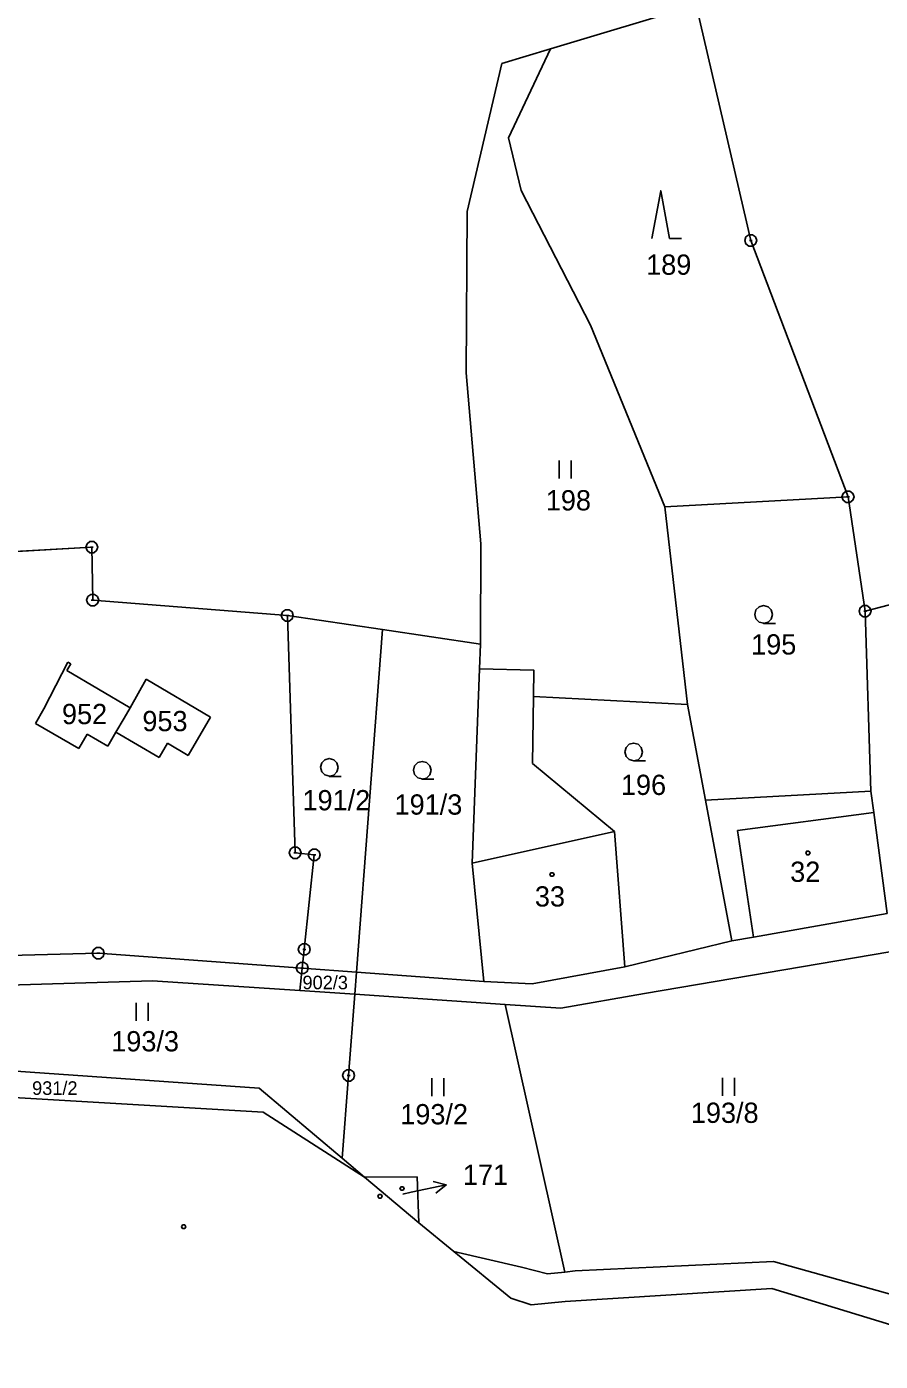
# Model space of a CAD drawing. Extents: x -580551 to -575069, y -1073031 to -1067931.
# Drawn here: x -576922.3 to -576850.7, y -1069930.4 to -1069818.4 of the extents above; entities that cross this region are included whole.
import ezdxf

# ---------------------------------------------------------------- set-up
doc = ezdxf.new("R2010")
doc.units = 0
for name, color, linetype in [('Druh pozemku', 7, 'Continuous'), ('Geodetické body', 7, 'Continuous'), ('Hranice z DKM', 7, 'Continuous'), ('Katastrální hranice', 7, 'Continuous'), ('Parcela', 7, 'Continuous'), ('Parcelní číslo', 7, 'Continuous'), ('Parcelní číslo_stavba', 7, 'Continuous'), ('Pomocná vrstva', 7, 'Continuous'), ('SR - hranice státu', 7, 'Continuous'), ('Vnitřní kresba', 7, 'Continuous'), ('Vrstva 6', 7, 'Continuous')]:
    doc.layers.add(name, color=color, linetype=linetype)

msp = doc.modelspace()

# ---------------------------------------------------------------- linework, layer by layer
at = {"layer": 'Druh pozemku'}
for p, q in [((-576877.6, -1069854.79), (-576877.6, -1069856.29)), ((-576876.6, -1069856.29), (-576876.6, -1069854.79)), ((-576913.12, -1069900.29), (-576913.12, -1069901.79)), ((-576912.12, -1069901.79), (-576912.12, -1069900.29)), ((-576888.3, -1069906.61), (-576888.3, -1069908.11)), ((-576887.3, -1069908.11), (-576887.3, -1069906.61)), ((-576863.9, -1069906.59), (-576863.9, -1069908.09)), ((-576862.9, -1069908.09), (-576862.9, -1069906.59))]:
    msp.add_line(p, q, dxfattribs=at)
for points in [[(-576869.84, -1069836.16), (-576869.09, -1069832.16), (-576868.34, -1069836.16), (-576867.34, -1069836.16)], [(-576860.44, -1069868.44), (-576860.82, -1069868.34), (-576861.09, -1069868.07), (-576861.19, -1069867.7), (-576861.09, -1069867.33), (-576860.82, -1069867.06), (-576860.45, -1069866.96), (-576860.08, -1069867.06), (-576859.81, -1069867.33), (-576859.71, -1069867.71), (-576859.81, -1069868.09), (-576860.08, -1069868.36), (-576860.46, -1069868.46), (-576859.46, -1069868.46)], [(-576871.35, -1069879.98), (-576871.73, -1069879.88), (-576872, -1069879.61), (-576872.1, -1069879.24), (-576872, -1069878.87), (-576871.73, -1069878.6), (-576871.36, -1069878.5), (-576870.99, -1069878.6), (-576870.72, -1069878.87), (-576870.62, -1069879.25), (-576870.72, -1069879.63), (-576870.99, -1069879.9), (-576871.37, -1069880), (-576870.37, -1069880)], [(-576896.9, -1069881.27), (-576897.28, -1069881.17), (-576897.55, -1069880.9), (-576897.65, -1069880.53), (-576897.55, -1069880.16), (-576897.28, -1069879.89), (-576896.91, -1069879.79), (-576896.54, -1069879.89), (-576896.27, -1069880.16), (-576896.17, -1069880.54), (-576896.27, -1069880.92), (-576896.54, -1069881.19), (-576896.92, -1069881.29), (-576895.92, -1069881.29)], [(-576889.1, -1069881.51), (-576889.48, -1069881.41), (-576889.75, -1069881.14), (-576889.85, -1069880.77), (-576889.75, -1069880.4), (-576889.48, -1069880.13), (-576889.11, -1069880.03), (-576888.74, -1069880.13), (-576888.47, -1069880.4), (-576888.37, -1069880.78), (-576888.47, -1069881.16), (-576888.74, -1069881.43), (-576889.12, -1069881.53), (-576888.12, -1069881.53)]]:
    msp.add_lwpolyline(points, dxfattribs=at)
for points in [[(-576856.64, -1069887.56), (-576856.55, -1069887.71), (-576856.64, -1069887.86), (-576856.82, -1069887.86), (-576856.91, -1069887.71), (-576856.82, -1069887.56)], [(-576878.12, -1069889.37), (-576878.03, -1069889.52), (-576878.12, -1069889.67), (-576878.3, -1069889.67), (-576878.39, -1069889.52), (-576878.3, -1069889.37)], [(-576892.56, -1069916.37), (-576892.47, -1069916.52), (-576892.56, -1069916.67), (-576892.74, -1069916.67), (-576892.83, -1069916.52), (-576892.74, -1069916.37)], [(-576890.71, -1069915.71), (-576890.62, -1069915.86), (-576890.71, -1069916.01), (-576890.89, -1069916.01), (-576890.98, -1069915.86), (-576890.89, -1069915.71)], [(-576909.05, -1069918.92), (-576908.96, -1069919.07), (-576909.05, -1069919.22), (-576909.23, -1069919.22), (-576909.32, -1069919.07), (-576909.23, -1069918.92)]]:
    msp.add_lwpolyline(points, close=True, dxfattribs=at)
at = {"layer": 'Geodetické body'}
for p, q in [((-576861.64, -1069836.34), (-576861.4, -1069836.34)), ((-576853.48, -1069857.85), (-576853.24, -1069857.85)), ((-576916.96, -1069862.07), (-576916.72, -1069862.07)), ((-576916.89, -1069866.51), (-576916.65, -1069866.51)), ((-576900.55, -1069867.8), (-576900.31, -1069867.8)), ((-576852.04, -1069867.44), (-576851.8, -1069867.44)), ((-576899.89, -1069887.71), (-576899.65, -1069887.71)), ((-576898.29, -1069887.88), (-576898.05, -1069887.88)), ((-576916.42, -1069896.13), (-576916.18, -1069896.13)), ((-576899.13, -1069895.81), (-576898.89, -1069895.81)), ((-576899.3, -1069897.38), (-576899.06, -1069897.38)), ((-576895.41, -1069906.39), (-576895.17, -1069906.39))]:
    msp.add_line(p, q, dxfattribs=at)
for points in [[(-576861.37, -1069835.86), (-576861.12, -1069836.04), (-576861.02, -1069836.33), (-576861.12, -1069836.62), (-576861.37, -1069836.8), (-576861.68, -1069836.8), (-576861.93, -1069836.62), (-576862.03, -1069836.33), (-576861.93, -1069836.04), (-576861.68, -1069835.86)], [(-576853.21, -1069857.37), (-576852.96, -1069857.55), (-576852.86, -1069857.84), (-576852.96, -1069858.13), (-576853.21, -1069858.31), (-576853.52, -1069858.31), (-576853.77, -1069858.13), (-576853.87, -1069857.84), (-576853.77, -1069857.55), (-576853.52, -1069857.37)], [(-576916.69, -1069861.59), (-576916.44, -1069861.77), (-576916.34, -1069862.06), (-576916.44, -1069862.35), (-576916.69, -1069862.53), (-576917, -1069862.53), (-576917.25, -1069862.35), (-576917.35, -1069862.06), (-576917.25, -1069861.77), (-576917, -1069861.59)], [(-576916.62, -1069866.03), (-576916.37, -1069866.21), (-576916.27, -1069866.5), (-576916.37, -1069866.79), (-576916.62, -1069866.97), (-576916.93, -1069866.97), (-576917.18, -1069866.79), (-576917.28, -1069866.5), (-576917.18, -1069866.21), (-576916.93, -1069866.03)], [(-576900.28, -1069867.32), (-576900.03, -1069867.5), (-576899.93, -1069867.79), (-576900.03, -1069868.08), (-576900.28, -1069868.26), (-576900.59, -1069868.26), (-576900.84, -1069868.08), (-576900.94, -1069867.79), (-576900.84, -1069867.5), (-576900.59, -1069867.32)], [(-576851.77, -1069866.96), (-576851.52, -1069867.14), (-576851.42, -1069867.43), (-576851.52, -1069867.72), (-576851.77, -1069867.9), (-576852.08, -1069867.9), (-576852.33, -1069867.72), (-576852.43, -1069867.43), (-576852.33, -1069867.14), (-576852.08, -1069866.96)], [(-576899.62, -1069887.23), (-576899.37, -1069887.41), (-576899.27, -1069887.7), (-576899.37, -1069887.99), (-576899.62, -1069888.17), (-576899.93, -1069888.17), (-576900.18, -1069887.99), (-576900.28, -1069887.7), (-576900.18, -1069887.41), (-576899.93, -1069887.23)], [(-576898.02, -1069887.4), (-576897.77, -1069887.58), (-576897.67, -1069887.87), (-576897.77, -1069888.16), (-576898.02, -1069888.34), (-576898.33, -1069888.34), (-576898.58, -1069888.16), (-576898.68, -1069887.87), (-576898.58, -1069887.58), (-576898.33, -1069887.4)], [(-576898.86, -1069895.33), (-576898.61, -1069895.51), (-576898.51, -1069895.8), (-576898.61, -1069896.09), (-576898.86, -1069896.27), (-576899.17, -1069896.27), (-576899.42, -1069896.09), (-576899.52, -1069895.8), (-576899.42, -1069895.51), (-576899.17, -1069895.33)], [(-576916.15, -1069895.65), (-576915.9, -1069895.83), (-576915.8, -1069896.12), (-576915.9, -1069896.41), (-576916.15, -1069896.59), (-576916.46, -1069896.59), (-576916.71, -1069896.41), (-576916.81, -1069896.12), (-576916.71, -1069895.83), (-576916.46, -1069895.65)], [(-576899.03, -1069896.9), (-576898.78, -1069897.08), (-576898.68, -1069897.37), (-576898.78, -1069897.66), (-576899.03, -1069897.84), (-576899.34, -1069897.84), (-576899.59, -1069897.66), (-576899.69, -1069897.37), (-576899.59, -1069897.08), (-576899.34, -1069896.9)], [(-576895.14, -1069905.91), (-576894.89, -1069906.09), (-576894.79, -1069906.38), (-576894.89, -1069906.67), (-576895.14, -1069906.85), (-576895.45, -1069906.85), (-576895.7, -1069906.67), (-576895.8, -1069906.38), (-576895.7, -1069906.09), (-576895.45, -1069905.91)]]:
    msp.add_lwpolyline(points, close=True, dxfattribs=at)
at = {"layer": 'Hranice z DKM'}
msp.add_lwpolyline([(-576884.21, -1069870.2), (-576884.19, -1069861.78), (-576885.42, -1069847.43), (-576885.34, -1069833.9), (-576882.42, -1069821.5), (-576878.33, -1069820.27), (-576881.87, -1069827.71), (-576880.79, -1069832.14), (-576874.99, -1069843.44), (-576868.75, -1069858.68)], dxfattribs=at)
at = {"layer": 'Katastrální hranice'}
for p, q in [((-576902.47, -1069909.45), (-576936.44, -1069907.45)), ((-576893.96, -1069914.9), (-576902.47, -1069909.45)), ((-576889.39, -1069918.74), (-576893.96, -1069914.9)), ((-576886.45, -1069921.15), (-576889.39, -1069918.74)), ((-576881.68, -1069925.06), (-576886.45, -1069921.15)), ((-576859.77, -1069924.26), (-576877.11, -1069925.34)), ((-576839.68, -1069930.36), (-576859.77, -1069924.26)), ((-576879.96, -1069925.62), (-576881.68, -1069925.06)), ((-576877.11, -1069925.34), (-576879.96, -1069925.62))]:
    msp.add_line(p, q, dxfattribs=at)
at = {"layer": 'Parcela'}
for p, q in [((-576866.12, -1069816.6), (-576878.33, -1069820.27)), ((-576866.12, -1069816.6), (-576861.52, -1069836.34)), ((-576878.33, -1069820.27), (-576882.42, -1069821.5)), ((-576881.87, -1069827.71), (-576878.33, -1069820.27)), ((-576882.42, -1069821.5), (-576885.34, -1069833.9)), ((-576880.79, -1069832.14), (-576881.87, -1069827.71)), ((-576874.99, -1069843.44), (-576880.79, -1069832.14)), ((-576885.34, -1069833.9), (-576885.42, -1069847.43)), ((-576861.52, -1069836.34), (-576853.36, -1069857.85)), ((-576868.75, -1069858.68), (-576874.99, -1069843.44)), ((-576885.42, -1069847.43), (-576884.19, -1069861.78)), ((-576810.54, -1069856.67), (-576851.92, -1069867.44)), ((-576853.36, -1069857.85), (-576868.75, -1069858.68)), ((-576853.36, -1069857.85), (-576851.92, -1069867.44)), ((-576868.75, -1069858.68), (-576866.85, -1069875.26)), ((-576926.56, -1069862.61), (-576916.84, -1069862.07)), ((-576916.84, -1069862.07), (-576916.77, -1069866.51)), ((-576884.21, -1069870.2), (-576884.19, -1069861.78)), ((-576916.77, -1069866.51), (-576900.43, -1069867.8)), ((-576900.43, -1069867.8), (-576899.77, -1069887.71)), ((-576900.43, -1069867.8), (-576892.44, -1069868.98)), ((-576851.92, -1069867.44), (-576851.44, -1069882.54)), ((-576892.44, -1069868.98), (-576894.63, -1069897.71)), ((-576892.44, -1069868.98), (-576884.21, -1069870.2)), ((-576884.29, -1069872.27), (-576884.21, -1069870.2)), ((-576920.87, -1069875.63), (-576918.87, -1069871.7)), ((-576918.62, -1069871.86), (-576918.87, -1069871.7)), ((-576918.95, -1069872.41), (-576918.62, -1069871.86)), ((-576913.64, -1069875.53), (-576918.95, -1069872.41)), ((-576884.91, -1069888.57), (-576884.29, -1069872.27)), ((-576879.74, -1069872.37), (-576884.29, -1069872.27)), ((-576879.77, -1069874.59), (-576879.74, -1069872.37)), ((-576913.64, -1069875.53), (-576912.28, -1069873.13)), ((-576912.28, -1069873.13), (-576906.87, -1069876.31)), ((-576879.85, -1069880.22), (-576879.77, -1069874.59)), ((-576866.85, -1069875.26), (-576879.77, -1069874.59)), ((-576921.58, -1069876.85), (-576920.87, -1069875.63)), ((-576914.13, -1069876.4), (-576913.64, -1069875.53)), ((-576906.87, -1069876.31), (-576908.76, -1069879.53)), ((-576866.85, -1069875.26), (-576865.34, -1069883.29)), ((-576917.94, -1069878.95), (-576921.58, -1069876.85)), ((-576914.82, -1069877.59), (-576914.13, -1069876.4)), ((-576917.24, -1069877.75), (-576917.94, -1069878.95)), ((-576915.5, -1069878.76), (-576917.24, -1069877.75)), ((-576914.82, -1069877.59), (-576915.5, -1069878.76)), ((-576911.2, -1069879.7), (-576914.82, -1069877.59)), ((-576910.5, -1069878.51), (-576911.2, -1069879.7)), ((-576908.76, -1069879.53), (-576910.5, -1069878.51)), ((-576872.98, -1069885.92), (-576879.85, -1069880.22)), ((-576851.44, -1069882.54), (-576865.34, -1069883.29)), ((-576851.44, -1069882.54), (-576851.2, -1069884.33)), ((-576865.34, -1069883.29), (-576863.13, -1069895.1)), ((-576851.2, -1069884.33), (-576850.08, -1069892.79)), ((-576872.11, -1069897.27), (-576872.98, -1069885.92)), ((-576899.77, -1069887.71), (-576898.17, -1069887.88)), ((-576898.17, -1069887.88), (-576899.01, -1069895.81)), ((-576883.93, -1069898.49), (-576884.91, -1069888.57)), ((-576850.08, -1069892.79), (-576861.3, -1069894.78)), ((-576863.13, -1069895.1), (-576872.11, -1069897.27)), ((-576861.3, -1069894.78), (-576863.13, -1069895.1)), ((-576916.3, -1069896.13), (-576949.74, -1069896.96)), ((-576899.18, -1069897.38), (-576916.3, -1069896.13)), ((-576899.01, -1069895.81), (-576899.18, -1069897.38)), ((-576849.85, -1069896), (-576870.44, -1069899.5)), ((-576899.18, -1069897.38), (-576899.39, -1069899.26)), ((-576899.18, -1069897.38), (-576894.63, -1069897.71)), ((-576879.87, -1069898.69), (-576872.11, -1069897.27)), ((-576911.76, -1069898.43), (-576931.95, -1069899.07)), ((-576911.76, -1069898.43), (-576899.39, -1069899.26)), ((-576894.63, -1069897.71), (-576894.77, -1069899.57)), ((-576894.63, -1069897.71), (-576883.93, -1069898.49)), ((-576883.93, -1069898.49), (-576879.87, -1069898.69)), ((-576899.39, -1069899.26), (-576894.77, -1069899.57)), ((-576894.77, -1069899.57), (-576895.29, -1069906.39)), ((-576894.77, -1069899.57), (-576882.15, -1069900.42)), ((-576870.44, -1069899.5), (-576877.48, -1069900.73)), ((-576882.15, -1069900.42), (-576877.48, -1069900.73)), ((-576934.29, -1069905.26), (-576902.79, -1069907.45)), ((-576895.29, -1069906.39), (-576895.82, -1069913.33)), ((-576895.82, -1069913.33), (-576902.79, -1069907.45)), ((-576893.96, -1069914.9), (-576895.82, -1069913.33)), ((-576889.52, -1069914.89), (-576893.96, -1069914.9)), ((-576889.52, -1069914.89), (-576889.39, -1069918.74)), ((-576880.78, -1069922.45), (-576886.45, -1069921.15)), ((-576859.63, -1069921.98), (-576876.27, -1069922.78)), ((-576840.51, -1069927.32), (-576859.63, -1069921.98)), ((-576878.58, -1069923.03), (-576880.78, -1069922.45)), ((-576877.13, -1069922.87), (-576878.58, -1069923.03)), ((-576876.27, -1069922.78), (-576877.13, -1069922.87))]:
    msp.add_line(p, q, dxfattribs=at)
at = {"layer": 'Pomocná vrstva'}
for p in [(-576890.75, -1069916.33), (-576887.094, -1069915.562)]:
    msp.add_line(p, (-576890.03, -1069916.18), dxfattribs=at)
msp.add_lwpolyline([(-576888.176, -1069915.278), (-576887.094, -1069915.562), (-576887.97, -1069916.257)], dxfattribs=at)
at = {"layer": 'SR - hranice státu'}
for points in [[(-576851.92, -1069867.44), (-576810.54, -1069856.67), (-576816.53, -1069845.21), (-576822.88, -1069828.95)], [(-576868.75, -1069858.68), (-576853.36, -1069857.85), (-576851.92, -1069867.44)], [(-576884.21, -1069870.2), (-576884.29, -1069872.27), (-576879.74, -1069872.37), (-576879.77, -1069874.59), (-576866.85, -1069875.26), (-576868.75, -1069858.68)], [(-576942.98, -1069866), (-576926.45, -1069866.31), (-576926.56, -1069862.61), (-576916.84, -1069862.07), (-576916.77, -1069866.51), (-576900.43, -1069867.8)], [(-576900.43, -1069867.8), (-576892.44, -1069868.98), (-576884.21, -1069870.2)]]:
    msp.add_lwpolyline(points, dxfattribs=at)
at = {"layer": 'Vnitřní kresba'}
for p, q in [((-576851.2, -1069884.33), (-576862.65, -1069885.83)), ((-576884.91, -1069888.57), (-576872.98, -1069885.92)), ((-576862.65, -1069885.83), (-576861.3, -1069894.78))]:
    msp.add_line(p, q, dxfattribs=at)
at = {"layer": 'Vrstva 6'}
msp.add_line((-576877.13, -1069922.87), (-576882.15, -1069900.42), dxfattribs=at)

# ---------------------------------------------------------------- texts
at = {"layer": 'Parcelní číslo'}
for s, height, p in [('189', 1.7, (-576870.311, -1069839.21)), ('198', 1.7, (-576878.735, -1069858.98)), ('195', 1.7, (-576861.499, -1069871.07)), ('952', 1.7, (-576919.351, -1069876.91)), ('953', 1.7, (-576912.602, -1069877.5)), ('196', 1.7, (-576872.427, -1069882.85)), ('191/2', 1.7, (-576899.16, -1069884.14)), ('191/3', 1.7, (-576891.432, -1069884.5)), ('902/3', 1.14, (-576899.16, -1069899.15)), ('193/3', 1.7, (-576915.216, -1069904.36)), ('931/2', 1.14, (-576921.859, -1069908.01)), ('193/2', 1.7, (-576890.954, -1069910.48)), ('193/8', 1.7, (-576866.557, -1069910.36))]:
    msp.add_text(s, height=height, dxfattribs=at).set_placement(p)
at = {"layer": 'Parcelní číslo_stavba'}
for s, height, p in [('32', 1.7, (-576858.218, -1069890.14)), ('33', 1.7, (-576879.65, -1069892.21)), ('171', 0.1, (-576890.822, -1069916.33))]:
    msp.add_text(s, height=height, dxfattribs=at).set_placement(p)
at = {"layer": 'Pomocná vrstva'}
msp.add_text('171', height=1.7, dxfattribs=at).set_placement((-576885.697, -1069915.56))

doc.saveas('drawing.dxf')
